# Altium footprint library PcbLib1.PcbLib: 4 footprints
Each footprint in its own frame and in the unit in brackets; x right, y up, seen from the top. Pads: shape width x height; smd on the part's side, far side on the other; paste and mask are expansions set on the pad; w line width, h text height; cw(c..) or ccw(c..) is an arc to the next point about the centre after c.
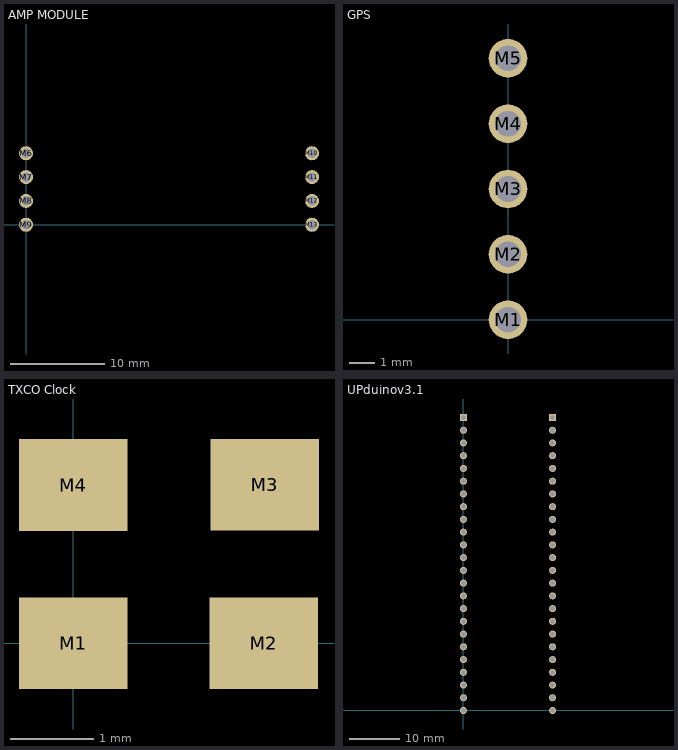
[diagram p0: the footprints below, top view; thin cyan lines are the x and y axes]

## AMP MODULE [mm]
pads (8):
  round 1.5 hole 1: M6(0,7.62) M7(0,5.08) M8(0,2.54) M9(0,0) M10(30.48,7.62) M11(30.48,5.08) M12(30.48,2.54) M13(30.48,0)

## GPS [mm]
pads (5):
  round 1.5 hole 1: M1(0,0) M2(0,2.54) M3(0,5.08) M4(0,7.62) M5(0,10.16)

## TXCO Clock [mm]
pads (4):
  rect 1.3x1.1 smd: M1(0,0) M2(2.286,0) M3(2.3,1.905) M4(0,1.9)

## UPduinov3.1 [mm]
pads (48):
  round 1.4 hole 1: 1(0,0) 2(0,2.54) 3(0,5.08) 3v3(0,38.1) 4(0,7.62) 5(0,10.16) 6(0,12.7) 7(0,15.24) 8(0,17.78) 9(0,20.32) 10(0,22.86) 11(0,25.4) 13(17.78,33.02) 17(0,40.64) 18(17.78,27.94) 19(17.78,30.48) 20(17.78,48.26) 21(17.78,35.56) 22(0,53.34) 23(0,33.02) 25(0,30.48) 26(0,27.94) 27(17.78,5.08) 28(17.78,7.62) 29(17.78,10.16) 30(17.78,12.7) 31(17.78,15.24) 32(17.78,17.78) 33(17.78,20.32) 34(17.78,22.86) 35(17.78,25.4) 40(17.78,38.1) 42(17.78,43.18) 43(17.78,45.72) 44(0,48.26) 45(17.78,50.8) 46(17.78,53.34) 47(17.78,55.88) 50(17.78,0) 51(17.78,2.54) 52(0,55.88) 55(0,43.18) 56(0,45.72) 57(0,50.8) GND(0,35.56) GND(17.78,40.64)
  rect 1.4x1.4 hole 1: 48(17.78,58.42) GND(0,58.42)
